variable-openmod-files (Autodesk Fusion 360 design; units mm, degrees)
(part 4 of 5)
sketch "50mm PM Label" plane through (0, 0, 0) normal (0, 0, -1) x axis (1, 0, 0)
  line L1 (1, -18.9737) -> (1, -23.9792)
  line L2 (14.6475, -19.0119) -> (11.43, -15.1775)
  line L3 (9.9868, 4.6112) -> (6.5, 2.5981)
  line L4 (1, -6.9282) -> (1, -10.9545)
  line L5 (1, 16.9706) -> (1, 12.9615)
  line L6 (10.725, 7.3468) -> (14.1969, 9.3513)
  line L7 (-8.9868, 6.3433) -> (-5.5, 4.3301)
  line L8 (5.5, 4.3301) -> (8.9868, 6.3433)
  line L9 (-1, -16.9706) -> (-1, -12.9615)
  line L10 (-10.725, -7.3468) -> (-14.1969, -9.3513)
  line L11 (-11.725, 5.6147) -> (-15.1969, 7.6193)
  line L12 (-15.1969, -7.6193) -> (-11.725, -5.6147)
  line L13 (11.725, -5.6147) -> (15.1969, -7.6193)
  line L14 (15.1969, 7.6193) -> (11.725, 5.6147)
  line L15 (1, -12.9615) -> (1, -16.9706)
  line L16 (14.1969, -9.3513) -> (10.725, -7.3468)
  line L17 (-1, 12.9615) -> (-1, 16.9706)
  line L18 (-14.1969, 9.3513) -> (-10.725, 7.3468)
  line L19 (-1, -10.9545) -> (-1, -6.9282)
  line L20 (-6.5, 2.5981) -> (-9.9868, 4.6112)
  line L21 (-11.43, -15.1775) -> (-14.6475, -19.0119)
  line L22 (-1, -23.9792) -> (-1, -18.9737)
  line L23 (-18.5118, -4.2796) -> (-23.4412, -5.1487)
  line L24 (-16.1795, -17.7263) -> (-12.9621, -13.8919)
  line L25 (-16.9317, 8.6208) -> (-21.2666, 11.1236)
  line L26 (-23.7885, -3.1791) -> (-18.8591, -2.3099)
  line L27 (-7.4291, 17.4874) -> (-9.141, 22.191)
  line L28 (-20.2666, 12.8556) -> (-15.9317, 10.3529)
  line L29 (5.5497, 18.1714) -> (7.2617, 22.8751)
  line L30 (-7.2617, 22.8751) -> (-5.5497, 18.1714)
  line L31 (15.9317, 10.3529) -> (20.2666, 12.8556)
  line L32 (9.141, 22.191) -> (7.4291, 17.4874)
  line L33 (18.8591, -2.3099) -> (23.7885, -3.1791)
  line L34 (21.2666, 11.1236) -> (16.9317, 8.6208)
  line L35 (12.9621, -13.8919) -> (16.1795, -17.7263)
  line L36 (23.4412, -5.1487) -> (18.5118, -4.2796)
  line L37 (27.3973, 19.1838) -> (24.0432, 16.8352)
  line L38 (24.0432, -16.8352) -> (27.3973, -19.1838)
  line L39 (-17.7523, 28.4096) -> (-15.6326, 25.0174)
  line L40 (15.6326, 25.0174) -> (17.7523, 28.4096)
  line L41 (-27.3973, -19.1838) -> (-24.0432, -16.8352)
  line L42 (-24.0432, 16.8352) -> (-27.3973, 19.1838)
  line L43 (17.7523, -28.4096) -> (15.6326, -25.0174)
  line L44 (-15.6326, -25.0174) -> (-17.7523, -28.4096)
  curve K1 (0, 52) -> (0, 52)
  curve K2
  curve K3
  curve K4
  curve K5
  arc A1 centre (0, 0) radius 19 clockwise from (11.43, -15.1775) to (1, -18.9737)
  arc A2 centre (0, 0) radius 24 clockwise from (14.6475, -19.0119) to (1, -23.9792)
  arc A3 centre (0, 0) radius 11 clockwise from (9.9868, 4.6112) to (1, -10.9545)
  arc A4 centre (0, 0) radius 7 clockwise from (6.5, 2.5981) to (1, -6.9282)
  arc A5 centre (0, 0) radius 17 clockwise from (1, 16.9706) to (14.1969, 9.3513)
  arc A6 centre (0, 0) radius 13 clockwise from (1, 12.9615) to (10.725, 7.3468)
  circle C1 centre (0, 0) radius 5
  arc A7 centre (0, 0) radius 11 clockwise from (-8.9868, 6.3433) to (8.9868, 6.3433)
  arc A8 centre (0, 0) radius 7 clockwise from (-5.5, 4.3301) to (5.5, 4.3301)
  arc A9 centre (0, 0) radius 17 clockwise from (-1, -16.9706) to (-14.1969, -9.3513)
  arc A10 centre (0, 0) radius 13 clockwise from (-1, -12.9615) to (-10.725, -7.3468)
  arc A11 centre (0, 0) radius 17 clockwise from (-15.1969, -7.6193) to (-15.1969, 7.6193)
  arc A12 centre (0, 0) radius 13 clockwise from (-11.725, -5.6147) to (-11.725, 5.6147)
  arc A13 centre (0, 0) radius 17 clockwise from (15.1969, 7.6193) to (15.1969, -7.6193)
  arc A14 centre (0, 0) radius 13 clockwise from (11.725, 5.6147) to (11.725, -5.6147)
  arc A15 centre (0, 0) radius 17 clockwise from (14.1969, -9.3513) to (1, -16.9706)
  arc A16 centre (0, 0) radius 13 clockwise from (10.725, -7.3468) to (1, -12.9615)
  arc A17 centre (0, 0) radius 17 clockwise from (-14.1969, 9.3513) to (-1, 16.9706)
  arc A18 centre (0, 0) radius 13 clockwise from (-10.725, 7.3468) to (-1, 12.9615)
  arc A19 centre (0, 0) radius 11 clockwise from (-1, -10.9545) to (-9.9868, 4.6112)
  arc A20 centre (0, 0) radius 7 clockwise from (-1, -6.9282) to (-6.5, 2.5981)
  arc A21 centre (0, 0) radius 19 clockwise from (-1, -18.9737) to (-11.43, -15.1775)
  arc A22 centre (0, 0) radius 24 clockwise from (-1, -23.9792) to (-14.6475, -19.0119)
  arc A23 centre (0, 0) radius 19 clockwise from (-12.9621, -13.8919) to (-18.5118, -4.2796)
  arc A24 centre (0, 0) radius 24 clockwise from (-16.1795, -17.7263) to (-23.4412, -5.1487)
  arc A25 centre (0, 0) radius 19 clockwise from (-18.8591, -2.3099) to (-16.9317, 8.6208)
  arc A26 centre (0, 0) radius 24 clockwise from (-23.7885, -3.1791) to (-21.2666, 11.1236)
  arc A27 centre (0, 0) radius 19 clockwise from (-15.9317, 10.3529) to (-7.4291, 17.4874)
  arc A28 centre (0, 0) radius 24 clockwise from (-20.2666, 12.8556) to (-9.141, 22.191)
  arc A29 centre (0, 0) radius 19 clockwise from (-5.5497, 18.1714) to (5.5497, 18.1714)
  arc A30 centre (0, 0) radius 24 clockwise from (-7.2617, 22.8751) to (7.2617, 22.8751)
  arc A31 centre (0, 0) radius 19 clockwise from (7.4291, 17.4874) to (15.9317, 10.3529)
  arc A32 centre (0, 0) radius 24 clockwise from (9.141, 22.191) to (20.2666, 12.8556)
  arc A33 centre (0, 0) radius 19 clockwise from (16.9317, 8.6208) to (18.8591, -2.3099)
  arc A34 centre (0, 0) radius 24 clockwise from (21.2666, 11.1236) to (23.7885, -3.1791)
  arc A35 centre (0, 0) radius 24 clockwise from (23.4412, -5.1487) to (16.1795, -17.7263)
  arc A36 centre (0, 0) radius 19 clockwise from (18.5118, -4.2796) to (12.9621, -13.8919)
  closed curve K6 centre (0, 0)
  closed curve K7 centre (0, 0)
  arc A37 centre (0, 0) radius 33.5 clockwise from (-17.7523, 28.4096) to (17.7523, 28.4096)
  arc A38 centre (0, 0) radius 29.5 clockwise from (-15.6326, 25.0174) to (15.6326, 25.0174)
  closed curve K8 centre (0, 0)
  closed curve K9 centre (0, 0)
  arc A39 centre (0, 0) radius 33.5 clockwise from (17.7523, -28.4096) to (-17.7523, -28.4096)
  arc A40 centre (0, 0) radius 29.5 clockwise from (15.6326, -25.0174) to (-15.6326, -25.0174)
  circle C2 centre (-22.8469, 24.5003) radius 4
  circle C3 centre (22.8469, 24.5003) radius 4
  circle C4 centre (-22.8469, -24.5003) radius 4
  circle C5 centre (22.8469, -24.5003) radius 4
  coincident K1
  dimension "d517" Text1-Height = 10
extrude "Extrude28" cut sketch "50mm PM Label" against normal blind 0.5
sketch "50mm DC Label" plane through (0, 0, 20) normal (0, 0, -1) x axis (1, 0, 0)
  line L1 (8, 23.8964) -> (8, 32.5308)
  line L2 (-8, 32.5308) -> (-8, 23.8964)
  line L3 (27.3973, 19.1838) -> (24.0432, 16.8352)
  line L4 (24.0432, -16.8352) -> (27.3973, -19.1838)
  line L5 (17.7523, -28.4096) -> (15.6326, -25.0174)
  line L6 (-15.6326, -25.0174) -> (-17.7523, -28.4096)
  line L7 (-27.3973, -19.1838) -> (-24.0432, -16.8352)
  line L8 (-24.0432, 16.8352) -> (-27.3973, 19.1838)
  line L9 (6, 55.0308) -> (8, 54.1239)
  line L10 (-6, 55.0308) -> (6, 55.0308)
  line L11 (-8, 54.1239) -> (-6, 55.0308)
  curve K1
  curve K2
  curve K3
  curve K4
  line L12 (45, -1.2179) -> (45, -5.5)
  line L13 (48, -1.2179) -> (45, -1.2179)
  line L14 (48, 3.5) -> (48, -1.2179)
  line L15 (45, 3.5) -> (48, 3.5)
  line L16 (45, 5.5) -> (45, 3.5)
  line L17 (44.7744, 5.5) -> (45, 5.5)
  line L18 (-45, 5.5) -> (-44.7744, 5.5)
  line L19 (-45, 3.5) -> (-45, 5.5)
  line L20 (-48, 3.5) -> (-45, 3.5)
  line L21 (-48, -1.2179) -> (-48, 3.5)
  line L22 (-45, -1.2179) -> (-48, -1.2179)
  line L23 (-45, -5.5) -> (-45, -1.2179)
  line L24 (-44.7744, -5.5) -> (-45, -5.5)
  line L25 (45, -5.5) -> (44.7744, -5.5)
  arc A1 centre (0, 0) radius 25.2 clockwise from (8, 23.8964) to (-8, 23.8964)
  arc A2 centre (0, 0) radius 33.5 clockwise from (-8, 32.5308) to (8, 32.5308)
  closed curve K5 centre (0, 0)
  closed curve K6 centre (0, 0)
  arc A3 centre (0, 0) radius 27.5 clockwise from (26.4189, 7.6348) to (26.4189, -7.6348)
  closed curve K7 centre (0, 0)
  circle C1 centre (22.8469, -24.5003) radius 2.2
  circle C2 centre (22.8469, 24.5003) radius 2.2
  circle C3 centre (-22.8469, -24.5003) radius 2.2
  circle C4 centre (-22.8469, 24.5003) radius 2.2
  arc A4 centre (0, 0) radius 33.5 clockwise from (17.7523, -28.4096) to (-17.7523, -28.4096)
  arc A5 centre (0, 0) radius 29.5 clockwise from (15.6326, -25.0174) to (-15.6326, -25.0174)
  closed curve K8 centre (0, 0)
  closed curve K9 centre (0, 0)
  closed curve K10 centre (0, 0)
  closed curve K11 centre (0, 0)
  arc A6 centre (0, 0) radius 27.5 clockwise from (-26.4189, -7.6348) to (-26.4189, 7.6348)
  closed curve K12 centre (0, 0)
  closed curve K13 centre (0, 0)
  dimension "d520" Text1-Height = 10
extrude "Extrude29" cut sketch "50mm DC Label" against normal blind 0.5
sketch "52mm PM Label" plane through (0, 0, 0) normal (0, 0, -1) x axis (1, 0, 0)
  line L1 (101, -19.975) -> (101, -24.98)
  line L2 (115.2908, -19.7786) -> (112.0736, -15.9445)
  line L3 (109.9868, 4.6112) -> (106.5, 2.5981)
  line L4 (101, -6.9282) -> (101, -10.9545)
  line L5 (101, 17.9722) -> (101, 12.9615)
  line L6 (110.725, 7.3468) -> (115.0644, 9.8521)
  line L7 (91.0132, 6.3433) -> (94.5, 4.3301)
  line L8 (105.5, 4.3301) -> (108.9868, 6.3433)
  line L9 (99, -17.9722) -> (99, -12.9615)
  line L10 (89.275, -7.3468) -> (84.9356, -9.8521)
  line L11 (88.275, 5.6147) -> (83.9356, 8.1201)
  line L12 (83.9356, -8.1201) -> (88.275, -5.6147)
  line L13 (111.725, -5.6147) -> (116.0644, -8.1201)
  line L14 (116.0644, 8.1201) -> (111.725, 5.6147)
  line L15 (101, -12.9615) -> (101, -17.9722)
  line L16 (115.0644, -9.8521) -> (110.725, -7.3468)
  line L17 (99, 12.9615) -> (99, 17.9722)
  line L18 (84.9356, 9.8521) -> (89.275, 7.3468)
  line L19 (99, -10.9545) -> (99, -6.9282)
  line L20 (93.5, 2.5981) -> (90.0132, 4.6112)
  line L21 (87.9264, -15.9445) -> (84.7092, -19.7786)
  line L22 (99, -24.98) -> (99, -19.975)
  line L23 (80.5021, -4.4534) -> (75.5732, -5.3225)
  line L24 (83.1771, -18.493) -> (86.3943, -14.6589)
  line L25 (82.2012, 9.1215) -> (77.8667, 11.624)
  line L26 (75.2259, -3.3529) -> (80.1548, -2.4838)
  line L27 (92.2285, 18.4283) -> (90.5166, 23.1315)
  line L28 (78.8667, 13.356) -> (83.2012, 10.8535)
  line L29 (105.8922, 19.1124) -> (107.604, 23.8155)
  line L30 (92.396, 23.8155) -> (94.1078, 19.1124)
  line L31 (116.7988, 10.8535) -> (121.1333, 13.356)
  line L32 (109.4834, 23.1315) -> (107.7715, 18.4283)
  line L33 (119.8452, -2.4838) -> (124.7741, -3.3529)
  line L34 (122.1333, 11.624) -> (117.7988, 9.1215)
  line L35 (113.6057, -14.6589) -> (116.8229, -18.493)
  line L36 (124.4268, -5.3225) -> (119.4979, -4.4534)
  line L37 (127.3973, 19.1838) -> (124.8888, 17.4274)
  line L38 (124.8888, -17.4274) -> (127.3973, -19.1838)
  curve K1 (124.8888, -17.4274) -> (124.8888, 17.4274)
  line L39 (82.2477, 28.4096) -> (84.3674, 25.0174)
  line L40 (115.6326, 25.0174) -> (117.7523, 28.4096)
  line L41 (72.6027, -19.1838) -> (75.1112, -17.4274)
  line L42 (75.1112, 17.4274) -> (72.6027, 19.1838)
  curve K2 (75.1112, 17.4274) -> (75.1112, -17.4274)
  line L43 (117.7523, -28.4096) -> (115.6326, -25.0174)
  line L44 (84.3674, -25.0174) -> (82.2477, -28.4096)
  curve K3 (100, 52) -> (100, 52)
  curve K4
  curve K5
  curve K6
  curve K7
  arc A1 centre (100, 0) radius 20 clockwise from (112.0736, -15.9445) to (101, -19.975)
  arc A2 centre (100, 0) radius 25 clockwise from (115.2908, -19.7786) to (101, -24.98)
  arc A3 centre (100, 0) radius 11 clockwise from (109.9868, 4.6112) to (101, -10.9545)
  arc A4 centre (100, 0) radius 7 clockwise from (106.5, 2.5981) to (101, -6.9282)
  arc A5 centre (100, 0) radius 18 clockwise from (101, 17.9722) to (115.0644, 9.8521)
  arc A6 centre (100, 0) radius 13 clockwise from (101, 12.9615) to (110.725, 7.3468)
  circle C1 centre (100, 0) radius 5
  arc A7 centre (100, 0) radius 11 clockwise from (91.0132, 6.3433) to (108.9868, 6.3433)
  arc A8 centre (100, 0) radius 7 clockwise from (94.5, 4.3301) to (105.5, 4.3301)
  arc A9 centre (100, 0) radius 18 clockwise from (99, -17.9722) to (84.9356, -9.8521)
  arc A10 centre (100, 0) radius 13 clockwise from (99, -12.9615) to (89.275, -7.3468)
  arc A11 centre (100, 0) radius 18 clockwise from (83.9356, -8.1201) to (83.9356, 8.1201)
  arc A12 centre (100, 0) radius 13 clockwise from (88.275, -5.6147) to (88.275, 5.6147)
  arc A13 centre (100, 0) radius 18 clockwise from (116.0644, 8.1201) to (116.0644, -8.1201)
  arc A14 centre (100, 0) radius 13 clockwise from (111.725, 5.6147) to (111.725, -5.6147)
  arc A15 centre (100, 0) radius 18 clockwise from (115.0644, -9.8521) to (101, -17.9722)
  arc A16 centre (100, 0) radius 13 clockwise from (110.725, -7.3468) to (101, -12.9615)
  arc A17 centre (100, 0) radius 18 clockwise from (84.9356, 9.8521) to (99, 17.9722)
  arc A18 centre (100, 0) radius 13 clockwise from (89.275, 7.3468) to (99, 12.9615)
  arc A19 centre (100, 0) radius 11 clockwise from (99, -10.9545) to (90.0132, 4.6112)
  arc A20 centre (100, 0) radius 7 clockwise from (99, -6.9282) to (93.5, 2.5981)
  arc A21 centre (100, 0) radius 20 clockwise from (99, -19.975) to (87.9264, -15.9445)
  arc A22 centre (100, 0) radius 25 clockwise from (99, -24.98) to (84.7092, -19.7786)
  arc A23 centre (100, 0) radius 20 clockwise from (86.3943, -14.6589) to (80.5021, -4.4534)
  arc A24 centre (100, 0) radius 25 clockwise from (83.1771, -18.493) to (75.5732, -5.3225)
  arc A25 centre (100, 0) radius 20 clockwise from (80.1548, -2.4838) to (82.2012, 9.1215)
  arc A26 centre (100, 0) radius 25 clockwise from (75.2259, -3.3529) to (77.8667, 11.624)
  arc A27 centre (100, 0) radius 20 clockwise from (83.2012, 10.8535) to (92.2285, 18.4283)
  arc A28 centre (100, 0) radius 25 clockwise from (78.8667, 13.356) to (90.5166, 23.1315)
  arc A29 centre (100, 0) radius 20 clockwise from (94.1078, 19.1124) to (105.8922, 19.1124)
  arc A30 centre (100, 0) radius 25 clockwise from (92.396, 23.8155) to (107.604, 23.8155)
  arc A31 centre (100, 0) radius 20 clockwise from (107.7715, 18.4283) to (116.7988, 10.8535)
  arc A32 centre (100, 0) radius 25 clockwise from (109.4834, 23.1315) to (121.1333, 13.356)
  arc A33 centre (100, 0) radius 20 clockwise from (117.7988, 9.1215) to (119.8452, -2.4838)
  arc A34 centre (100, 0) radius 25 clockwise from (122.1333, 11.624) to (124.7741, -3.3529)
  arc A35 centre (100, 0) radius 25 clockwise from (124.4268, -5.3225) to (116.8229, -18.493)
  arc A36 centre (100, 0) radius 20 clockwise from (119.4979, -4.4534) to (113.6057, -14.6589)
  closed curve K8 centre (100, 0)
  arc A37 centre (100, 0) radius 33.5 clockwise from (82.2477, 28.4096) to (117.7523, 28.4096)
  arc A38 centre (100, 0) radius 29.5 clockwise from (84.3674, 25.0174) to (115.6326, 25.0174)
  closed curve K9 centre (100, 0)
  arc A39 centre (100, 0) radius 33.5 clockwise from (117.7523, -28.4096) to (82.2477, -28.4096)
  arc A40 centre (100, 0) radius 29.5 clockwise from (115.6326, -25.0174) to (84.3674, -25.0174)
  circle C2 centre (77.1531, 24.5003) radius 4
  circle C3 centre (122.8469, 24.5003) radius 4
  circle C4 centre (77.1531, -24.5003) radius 4
  circle C5 centre (122.8469, -24.5003) radius 4
  dimension "d523" Text1-Height = 10
sketch "52mm DC Label" plane through (0, 0, 20) normal (0, 0, -1) x axis (1, 0, 0)
  line L1 (117.7523, -28.4096) -> (115.6326, -25.0174)
  line L2 (84.3674, -25.0174) -> (82.2477, -28.4096)
  curve K1 (124.8888, 17.4274) -> (127.1497, 9.3052)
  line L3 (127.3973, 19.1838) -> (124.8888, 17.4274)
  line L4 (124.8888, -17.4274) -> (127.3973, -19.1838)
  curve K2 (127.1497, -9.3052) -> (124.8888, -17.4274)
  line L5 (108, 24.9487) -> (108, 32.5308)
  line L6 (92, 32.5308) -> (92, 24.9487)
  curve K3 (75.1112, -17.4274) -> (72.8503, -9.3052)
  line L7 (72.6027, -19.1838) -> (75.1112, -17.4274)
  line L8 (75.1112, 17.4274) -> (72.6027, 19.1838)
  curve K4 (72.8503, 9.3052) -> (75.1112, 17.4274)
  line L9 (106, 55.0308) -> (108, 54.1239)
  line L10 (94, 55.0308) -> (106, 55.0308)
  line L11 (92, 54.1239) -> (94, 55.0308)
  curve K5
  curve K6
  curve K7
  curve K8
  line L12 (145, -1.2179) -> (145, -5.5)
  line L13 (148, -1.2179) -> (145, -1.2179)
  line L14 (148, 3.5) -> (148, -1.2179)
  line L15 (145, 3.5) -> (148, 3.5)
  line L16 (145, 5.5) -> (145, 3.5)
  line L17 (144.7744, 5.5) -> (145, 5.5)
  line L18 (55, 5.5) -> (55.2256, 5.5)
  line L19 (55, 3.5) -> (55, 5.5)
  line L20 (52, 3.5) -> (55, 3.5)
  line L21 (52, -1.2179) -> (52, 3.5)
  line L22 (55, -1.2179) -> (52, -1.2179)
  line L23 (55, -5.5) -> (55, -1.2179)
  line L24 (55.2256, -5.5) -> (55, -5.5)
  line L25 (145, -5.5) -> (144.7744, -5.5)
  arc A1 centre (100, 0) radius 33.5 clockwise from (117.7523, -28.4096) to (82.2477, -28.4096)
  arc A2 centre (100, 0) radius 29.5 clockwise from (115.6326, -25.0174) to (84.3674, -25.0174)
  closed curve K9 centre (100, 0)
  arc A3 centre (100, 0) radius 28.7 clockwise from (127.1497, 9.3052) to (127.1497, -9.3052)
  arc A4 centre (100, 0) radius 26.2 clockwise from (108, 24.9487) to (92, 24.9487)
  arc A5 centre (100, 0) radius 33.5 clockwise from (92, 32.5308) to (108, 32.5308)
  closed curve K10 centre (100, 0)
  arc A6 centre (100, 0) radius 28.7 clockwise from (72.8503, -9.3052) to (72.8503, 9.3052)
  circle C1 centre (122.8469, -24.5003) radius 2.2
  circle C2 centre (122.8469, 24.5003) radius 2.2
  circle C3 centre (77.1531, -24.5003) radius 2.2
  circle C4 centre (77.1531, 24.5003) radius 2.2
  closed curve K11 centre (100, 0)
  closed curve K12 centre (100, 0)
  closed curve K13 centre (100, 0)
  dimension "d524" Text1-Height = 10
extrude "Extrude14" cut sketch "52mm PM Label" against normal blind 0.5
extrude "Extrude15" cut sketch "52mm DC Label" against normal blind 0.5
sketch "40mm PM Label" plane through (0, 0, 0) normal (0, 0, -1) x axis (1, 0, 0)
  line L1 (-1, -130.9545) -> (-1, -126.9282)
  line L2 (-6.5, -117.4019) -> (-9.9868, -115.3888)
  line L3 (-1, -107.0385) -> (-1, -103.0294)
  line L4 (-14.1969, -110.6487) -> (-10.725, -112.6532)
  line L5 (1, -132.9615) -> (1, -136.9706)
  line L6 (14.1969, -129.3513) -> (10.725, -127.3468)
  line L7 (11.725, -125.6147) -> (15.1969, -127.6193)
  line L8 (15.1969, -112.3807) -> (11.725, -114.3853)
  line L9 (-11.725, -114.3853) -> (-15.1969, -112.3807)
  line L10 (-15.1969, -127.6193) -> (-11.725, -125.6147)
  line L11 (-1, -136.9706) -> (-1, -132.9615)
  line L12 (-10.725, -127.3468) -> (-14.1969, -129.3513)
  line L13 (-8.9868, -113.6567) -> (-5.5, -115.6699)
  line L14 (5.5, -115.6699) -> (8.9868, -113.6567)
  line L15 (1, -103.0294) -> (1, -107.0385)
  line L16 (10.725, -112.6532) -> (14.1969, -110.6487)
  line L17 (9.9868, -115.3888) -> (6.5, -117.4019)
  line L18 (1, -126.9282) -> (1, -130.9545)
  line L19 (27.3973, -100.8162) -> (24.0432, -103.1648)
  line L20 (24.0432, -136.8352) -> (27.3973, -139.1838)
  line L21 (-17.7523, -91.5904) -> (-15.6326, -94.9826)
  line L22 (15.6326, -94.9826) -> (17.7523, -91.5904)
  line L23 (-27.3973, -139.1838) -> (-24.0432, -136.8352)
  line L24 (-24.0432, -103.1648) -> (-27.3973, -100.8162)
  line L25 (17.7523, -148.4096) -> (15.6326, -145.0174)
  line L26 (-15.6326, -145.0174) -> (-17.7523, -148.4096)
  curve K1 (0, -68) -> (0, -68)
  curve K2
  curve K3
  curve K4
  curve K5
  arc A1 centre (0, -120) radius 11 clockwise from (-1, -130.9545) to (-9.9868, -115.3888)
  arc A2 centre (0, -120) radius 7 clockwise from (-1, -126.9282) to (-6.5, -117.4019)
  arc A3 centre (0, -120) radius 17 clockwise from (-14.1969, -110.6487) to (-1, -103.0294)
  arc A4 centre (0, -120) radius 13 clockwise from (-10.725, -112.6532) to (-1, -107.0385)
  arc A5 centre (0, -120) radius 17 clockwise from (14.1969, -129.3513) to (1, -136.9706)
  arc A6 centre (0, -120) radius 13 clockwise from (10.725, -127.3468) to (1, -132.9615)
  arc A7 centre (0, -120) radius 17 clockwise from (15.1969, -112.3807) to (15.1969, -127.6193)
  arc A8 centre (0, -120) radius 13 clockwise from (11.725, -114.3853) to (11.725, -125.6147)
  arc A9 centre (0, -120) radius 17 clockwise from (-15.1969, -127.6193) to (-15.1969, -112.3807)
  arc A10 centre (0, -120) radius 13 clockwise from (-11.725, -125.6147) to (-11.725, -114.3853)
  arc A11 centre (0, -120) radius 17 clockwise from (-1, -136.9706) to (-14.1969, -129.3513)
  arc A12 centre (0, -120) radius 13 clockwise from (-1, -132.9615) to (-10.725, -127.3468)
  arc A13 centre (0, -120) radius 11 clockwise from (-8.9868, -113.6567) to (8.9868, -113.6567)
  arc A14 centre (0, -120) radius 7 clockwise from (-5.5, -115.6699) to (5.5, -115.6699)
  circle C1 centre (0, -120) radius 5
  arc A15 centre (0, -120) radius 17 clockwise from (1, -103.0294) to (14.1969, -110.6487)
  arc A16 centre (0, -120) radius 13 clockwise from (1, -107.0385) to (10.725, -112.6532)
  arc A17 centre (0, -120) radius 11 clockwise from (9.9868, -115.3888) to (1, -130.9545)
  arc A18 centre (0, -120) radius 7 clockwise from (6.5, -117.4019) to (1, -126.9282)
  closed curve K6 centre (0, -120)
  closed curve K7 centre (0, -120)
  arc A19 centre (0, -120) radius 33.5 clockwise from (-17.7523, -91.5904) to (17.7523, -91.5904)
  arc A20 centre (0, -120) radius 29.5 clockwise from (-15.6326, -94.9826) to (15.6326, -94.9826)
  closed curve K8 centre (0, -120)
  closed curve K9 centre (0, -120)
  arc A21 centre (0, -120) radius 33.5 clockwise from (17.7523, -148.4096) to (-17.7523, -148.4096)
  arc A22 centre (0, -120) radius 29.5 clockwise from (15.6326, -145.0174) to (-15.6326, -145.0174)
  circle C2 centre (-22.8469, -95.4997) radius 4
  circle C3 centre (22.8469, -95.4997) radius 4
  circle C4 centre (-22.8469, -144.5003) radius 4
  circle C5 centre (22.8469, -144.5003) radius 4
  dimension "d529" Text1-Height = 10
sketch "40mm DC Label" plane through (0, 0, 20) normal (0, 0, -1) x axis (1, 0, 0)
  line L1 (8, -101.1254) -> (8, -92.6458)
  line L2 (-8, -92.6458) -> (-8, -101.1254)
  line L3 (27.3973, -100.8162) -> (24.0432, -103.1648)
  line L4 (24.0432, -136.8352) -> (27.3973, -139.1838)
  line L5 (17.7523, -148.4096) -> (15.6326, -145.0174)
  line L6 (-15.6326, -145.0174) -> (-17.7523, -148.4096)
  line L7 (-27.3973, -139.1838) -> (-24.0432, -136.8352)
  line L8 (-24.0432, -103.1648) -> (-27.3973, -100.8162)
  line L9 (6, -64.9692) -> (8, -65.8761)
  line L10 (-6, -64.9692) -> (6, -64.9692)
  line L11 (-8, -65.8761) -> (-6, -64.9692)
  curve K1
  curve K2
  curve K3
  curve K4
  line L12 (45, -121.2179) -> (45, -125.5)
  line L13 (48, -121.2179) -> (45, -121.2179)
  line L14 (48, -116.5) -> (48, -121.2179)
  line L15 (45, -116.5) -> (48, -116.5)
  line L16 (45, -114.5) -> (45, -116.5)
  line L17 (44.7744, -114.5) -> (45, -114.5)
  line L18 (-45, -114.5) -> (-44.7744, -114.5)
  line L19 (-45, -116.5) -> (-45, -114.5)
  line L20 (-48, -116.5) -> (-45, -116.5)
  line L21 (-48, -121.2179) -> (-48, -116.5)
  line L22 (-45, -121.2179) -> (-48, -121.2179)
  line L23 (-45, -125.5) -> (-45, -121.2179)
  line L24 (-44.7744, -125.5) -> (-45, -125.5)
  line L25 (45, -125.5) -> (44.7744, -125.5)
  arc A1 centre (0, -120) radius 20.5 clockwise from (8, -101.1254) to (-8, -101.1254)
  arc A2 centre (0, -120) radius 28.5 clockwise from (-8, -92.6458) to (8, -92.6458)
  closed curve K5 centre (0, -120)
  closed curve K6 centre (0, -120)
  arc A3 centre (0, -120) radius 27.5 clockwise from (26.4189, -112.3652) to (26.4189, -127.6348)
  closed curve K7 centre (0, -120)
  circle C1 centre (22.8469, -144.5003) radius 2.2
  circle C2 centre (22.8469, -95.4997) radius 2.2
  circle C3 centre (-22.8469, -144.5003) radius 2.2
  circle C4 centre (-22.8469, -95.4997) radius 2.2
  arc A4 centre (0, -120) radius 33.5 clockwise from (17.7523, -148.4096) to (-17.7523, -148.4096)
  arc A5 centre (0, -120) radius 29.5 clockwise from (15.6326, -145.0174) to (-15.6326, -145.0174)
  closed curve K8 centre (0, -120)
  arc A6 centre (0, -120) radius 27.5 clockwise from (-26.4189, -127.6348) to (-26.4189, -112.3652)
  closed curve K9 centre (0, -120)
  closed curve K10 centre (0, -120)
  closed curve K11 centre (0, -120)
  closed curve K12 centre (0, -120)
  closed curve K13 centre (0, -120)
  dimension "d530" Text1-Height = 10
extrude "Extrude16" cut sketch "40mm DC Label" against normal blind 0.5
extrude "Extrude17" cut sketch "40mm PM Label" against normal blind 0.5
sketch "44mm PM Label" plane through (0, 0, 0) normal (0, 0, -1) x axis (1, 0, 0)
  line L1 (101, -138.9737) -> (101, -140.9762)
  line L2 (112.7172, -136.7115) -> (111.43, -135.1775)
  line L3 (109.9868, -115.3888) -> (106.5, -117.4019)
  line L4 (101, -126.9282) -> (101, -130.9545)
  line L5 (101, -103.0294) -> (101, -107.0385)
  line L6 (110.725, -112.6532) -> (114.1969, -110.6487)
  line L7 (91.0132, -113.6567) -> (94.5, -115.6699)
  line L8 (105.5, -115.6699) -> (108.9868, -113.6567)
  line L9 (99, -136.9706) -> (99, -132.9615)
  line L10 (89.275, -127.3468) -> (85.8031, -129.3513)
  line L11 (88.275, -114.3853) -> (84.8031, -112.3807)
  line L12 (84.8031, -127.6193) -> (88.275, -125.6147)
  line L13 (111.725, -125.6147) -> (115.1969, -127.6193)
  line L14 (115.1969, -112.3807) -> (111.725, -114.3853)
  line L15 (101, -132.9615) -> (101, -136.9706)
  line L16 (114.1969, -129.3513) -> (110.725, -127.3468)
  line L17 (99, -107.0385) -> (99, -103.0294)
  line L18 (85.8031, -110.6487) -> (89.275, -112.6532)
  line L19 (99, -130.9545) -> (99, -126.9282)
  line L20 (93.5, -117.4019) -> (90.0132, -115.3888)
  line L21 (88.57, -135.1775) -> (87.2828, -136.7115)
  line L22 (99, -140.9762) -> (99, -138.9737)
  line L23 (81.4882, -124.2796) -> (79.5161, -124.6273)
  line L24 (85.7507, -135.4259) -> (87.0379, -133.8919)
  line L25 (83.0683, -111.3792) -> (81.3341, -110.3779)
  line L26 (79.1689, -122.6577) -> (81.1409, -122.3099)
  line L27 (92.5709, -102.5126) -> (91.886, -100.6309)
  line L28 (82.3341, -108.6459) -> (84.0683, -109.6471)
  line L29 (105.5497, -101.8286) -> (106.2346, -99.9468)
  line L30 (93.7654, -99.9468) -> (94.4503, -101.8286)
  line L31 (115.9317, -109.6471) -> (117.6659, -108.6459)
  line L32 (108.114, -100.6309) -> (107.4291, -102.5126)
  line L33 (118.8591, -122.3099) -> (120.8311, -122.6577)
  line L34 (118.6659, -110.3779) -> (116.9317, -111.3792)
  line L35 (112.9621, -133.8919) -> (114.2493, -135.4259)
  line L36 (120.4839, -124.6273) -> (118.5118, -124.2796)
  line L37 (127.3973, -100.8162) -> (124.0432, -103.1648)
  line L38 (124.0432, -136.8352) -> (127.3973, -139.1838)
  line L39 (82.2477, -91.5904) -> (84.3674, -94.9826)
  line L40 (115.6326, -94.9826) -> (117.7523, -91.5904)
  line L41 (72.6027, -139.1838) -> (75.9568, -136.8352)
  line L42 (75.9568, -103.1648) -> (72.6027, -100.8162)
  line L43 (117.7523, -148.4096) -> (115.6326, -145.0174)
  line L44 (84.3674, -145.0174) -> (82.2477, -148.4096)
  curve K1 (100, -68) -> (100, -68)
  curve K2
  curve K3
  curve K4
  curve K5
  arc A1 centre (100, -120) radius 19 clockwise from (111.43, -135.1775) to (101, -138.9737)
  arc A2 centre (100, -120) radius 21 clockwise from (112.7172, -136.7115) to (101, -140.9762)
  arc A3 centre (100, -120) radius 11 clockwise from (109.9868, -115.3888) to (101, -130.9545)
  arc A4 centre (100, -120) radius 7 clockwise from (106.5, -117.4019) to (101, -126.9282)
  arc A5 centre (100, -120) radius 17 clockwise from (101, -103.0294) to (114.1969, -110.6487)
  arc A6 centre (100, -120) radius 13 clockwise from (101, -107.0385) to (110.725, -112.6532)
  circle C1 centre (100, -120) radius 5
  arc A7 centre (100, -120) radius 11 clockwise from (91.0132, -113.6567) to (108.9868, -113.6567)
  arc A8 centre (100, -120) radius 7 clockwise from (94.5, -115.6699) to (105.5, -115.6699)
  arc A9 centre (100, -120) radius 17 clockwise from (99, -136.9706) to (85.8031, -129.3513)
  arc A10 centre (100, -120) radius 13 clockwise from (99, -132.9615) to (89.275, -127.3468)
  arc A11 centre (100, -120) radius 17 clockwise from (84.8031, -127.6193) to (84.8031, -112.3807)
  arc A12 centre (100, -120) radius 13 clockwise from (88.275, -125.6147) to (88.275, -114.3853)
  arc A13 centre (100, -120) radius 17 clockwise from (115.1969, -112.3807) to (115.1969, -127.6193)
  arc A14 centre (100, -120) radius 13 clockwise from (111.725, -114.3853) to (111.725, -125.6147)
  arc A15 centre (100, -120) radius 17 clockwise from (114.1969, -129.3513) to (101, -136.9706)
  arc A16 centre (100, -120) radius 13 clockwise from (110.725, -127.3468) to (101, -132.9615)
  arc A17 centre (100, -120) radius 17 clockwise from (85.8031, -110.6487) to (99, -103.0294)
  arc A18 centre (100, -120) radius 13 clockwise from (89.275, -112.6532) to (99, -107.0385)
  arc A19 centre (100, -120) radius 11 clockwise from (99, -130.9545) to (90.0132, -115.3888)
  arc A20 centre (100, -120) radius 7 clockwise from (99, -126.9282) to (93.5, -117.4019)
  arc A21 centre (100, -120) radius 19 clockwise from (99, -138.9737) to (88.57, -135.1775)
  arc A22 centre (100, -120) radius 21 clockwise from (99, -140.9762) to (87.2828, -136.7115)
  arc A23 centre (100, -120) radius 19 clockwise from (87.0379, -133.8919) to (81.4882, -124.2796)
  arc A24 centre (100, -120) radius 21 clockwise from (85.7507, -135.4259) to (79.5161, -124.6273)
  arc A25 centre (100, -120) radius 19 clockwise from (81.1409, -122.3099) to (83.0683, -111.3792)
  arc A26 centre (100, -120) radius 21 clockwise from (79.1689, -122.6577) to (81.3341, -110.3779)
  arc A27 centre (100, -120) radius 19 clockwise from (84.0683, -109.6471) to (92.5709, -102.5126)
  arc A28 centre (100, -120) radius 21 clockwise from (82.3341, -108.6459) to (91.886, -100.6309)
  arc A29 centre (100, -120) radius 19 clockwise from (94.4503, -101.8286) to (105.5497, -101.8286)
  arc A30 centre (100, -120) radius 21 clockwise from (93.7654, -99.9468) to (106.2346, -99.9468)
  arc A31 centre (100, -120) radius 19 clockwise from (107.4291, -102.5126) to (115.9317, -109.6471)
  arc A32 centre (100, -120) radius 21 clockwise from (108.114, -100.6309) to (117.6659, -108.6459)
  arc A33 centre (100, -120) radius 19 clockwise from (116.9317, -111.3792) to (118.8591, -122.3099)
  arc A34 centre (100, -120) radius 21 clockwise from (118.6659, -110.3779) to (120.8311, -122.6577)
  arc A35 centre (100, -120) radius 21 clockwise from (120.4839, -124.6273) to (114.2493, -135.4259)
  arc A36 centre (100, -120) radius 19 clockwise from (118.5118, -124.2796) to (112.9621, -133.8919)
  closed curve K6 centre (100, -120)
  closed curve K7 centre (100, -120)
  arc A37 centre (100, -120) radius 33.5 clockwise from (82.2477, -91.5904) to (117.7523, -91.5904)
  arc A38 centre (100, -120) radius 29.5 clockwise from (84.3674, -94.9826) to (115.6326, -94.9826)
  closed curve K8 centre (100, -120)
  closed curve K9 centre (100, -120)
  arc A39 centre (100, -120) radius 33.5 clockwise from (117.7523, -148.4096) to (82.2477, -148.4096)
  arc A40 centre (100, -120) radius 29.5 clockwise from (115.6326, -145.0174) to (84.3674, -145.0174)
  circle C2 centre (77.1531, -95.4997) radius 4
  circle C3 centre (122.8469, -95.4997) radius 4
  circle C4 centre (77.1531, -144.5003) radius 4
  circle C5 centre (122.8469, -144.5003) radius 4
  dimension "d535" Text1-Height = 10
sketch "44mm DC Label" plane through (0, 0, 20) normal (0, 0, -1) x axis (1, 0, 0)
  line L1 (108, -99.2915) -> (108, -87.4692)
  line L2 (92, -87.4692) -> (92, -99.2915)
  line L3 (127.3973, -100.8162) -> (124.0432, -103.1648)
  line L4 (124.0432, -136.8352) -> (127.3973, -139.1838)
  line L5 (117.7523, -148.4096) -> (115.6326, -145.0174)
  line L6 (84.3674, -145.0174) -> (82.2477, -148.4096)
  line L7 (72.6027, -139.1838) -> (75.9568, -136.8352)
  line L8 (75.9568, -103.1648) -> (72.6027, -100.8162)
  line L9 (106, -64.9692) -> (108, -65.8761)
  line L10 (94, -64.9692) -> (106, -64.9692)
  line L11 (92, -65.8761) -> (94, -64.9692)
  curve K1
  curve K2
  curve K3
  curve K4
  line L12 (145, -121.2179) -> (145, -125.5)
  line L13 (148, -121.2179) -> (145, -121.2179)
  line L14 (148, -116.5) -> (148, -121.2179)
  line L15 (145, -116.5) -> (148, -116.5)
  line L16 (145, -114.5) -> (145, -116.5)
  line L17 (144.7744, -114.5) -> (145, -114.5)
  line L18 (55, -114.5) -> (55.2256, -114.5)
  line L19 (55, -116.5) -> (55, -114.5)
  line L20 (52, -116.5) -> (55, -116.5)
  line L21 (52, -121.2179) -> (52, -116.5)
  line L22 (55, -121.2179) -> (52, -121.2179)
  line L23 (55, -125.5) -> (55, -121.2179)
  line L24 (55.2256, -125.5) -> (55, -125.5)
  line L25 (145, -125.5) -> (144.7744, -125.5)
  arc A1 centre (100, -120) radius 22.2 clockwise from (108, -99.2915) to (92, -99.2915)
  arc A2 centre (100, -120) radius 33.5 clockwise from (92, -87.4692) to (108, -87.4692)
  closed curve K5 centre (100, -120)
  closed curve K6 centre (100, -120)
  arc A3 centre (100, -120) radius 27.5 clockwise from (126.4189, -112.3652) to (126.4189, -127.6348)
  closed curve K7 centre (100, -120)
  circle C1 centre (122.8469, -144.5003) radius 2.2
  circle C2 centre (122.8469, -95.4997) radius 2.2
  circle C3 centre (77.1531, -144.5003) radius 2.2
  circle C4 centre (77.1531, -95.4997) radius 2.2
  arc A4 centre (100, -120) radius 33.5 clockwise from (117.7523, -148.4096) to (82.2477, -148.4096)
  arc A5 centre (100, -120) radius 29.5 clockwise from (115.6326, -145.0174) to (84.3674, -145.0174)
  closed curve K8 centre (100, -120)
  closed curve K9 centre (100, -120)
  closed curve K10 centre (100, -120)
  closed curve K11 centre (100, -120)
  arc A6 centre (100, -120) radius 27.5 clockwise from (73.5811, -127.6348) to (73.5811, -112.3652)
  closed curve K12 centre (100, -120)
  closed curve K13 centre (100, -120)
  dimension "d536" Text1-Height = 10
extrude "Extrude18" cut sketch "44mm PM Label" against normal blind 0.5
extrude "Extrude19" cut sketch "44mm DC Label" against normal blind 0.5
sketch "45mm PM Label" plane through (0, 0, 0) normal (0, 0, -1) x axis (1, 0, 0)
  line L1 (201, -138.9737) -> (201, -141.4767)
  line L2 (213.0389, -137.0949) -> (211.43, -135.1775)
  line L3 (209.9868, -115.3888) -> (206.5, -117.4019)
  line L4 (201, -126.9282) -> (201, -130.9545)
  line L5 (201, -103.0294) -> (201, -107.0385)
  line L6 (210.725, -112.6532) -> (214.1969, -110.6487)
  line L7 (191.0132, -113.6567) -> (194.5, -115.6699)
  line L8 (205.5, -115.6699) -> (208.9868, -113.6567)
  line L9 (199, -136.9706) -> (199, -132.9615)
  line L10 (189.275, -127.3468) -> (185.8031, -129.3513)
  line L11 (188.275, -114.3853) -> (184.8031, -112.3807)
  line L12 (184.8031, -127.6193) -> (188.275, -125.6147)
  line L13 (211.725, -125.6147) -> (215.1969, -127.6193)
  line L14 (215.1969, -112.3807) -> (211.725, -114.3853)
  line L15 (201, -132.9615) -> (201, -136.9706)
  line L16 (214.1969, -129.3513) -> (210.725, -127.3468)
  line L17 (199, -107.0385) -> (199, -103.0294)
  line L18 (185.8031, -110.6487) -> (189.275, -112.6532)
  line L19 (199, -130.9545) -> (199, -126.9282)
  line L20 (193.5, -117.4019) -> (190.0132, -115.3888)
  line L21 (188.57, -135.1775) -> (186.9611, -137.0949)
  line L22 (199, -141.4767) -> (199, -138.9737)
  line L23 (181.4882, -124.2796) -> (179.0232, -124.7142)
  line L24 (185.429, -135.8093) -> (187.0379, -133.8919)
  line L25 (183.0683, -111.3792) -> (180.9006, -110.1277)
  line L26 (178.6759, -122.7446) -> (181.1409, -122.3099)
  line L27 (192.5709, -102.5126) -> (191.7148, -100.1605)
  line L28 (181.9006, -108.3956) -> (184.0683, -109.6471)
  line L29 (205.5497, -101.8286) -> (206.4058, -99.4765)
  line L30 (193.5942, -99.4765) -> (194.4503, -101.8286)
  line L31 (215.9317, -109.6471) -> (218.0994, -108.3956)
  line L32 (208.2852, -100.1605) -> (207.4291, -102.5126)
  line L33 (218.8591, -122.3099) -> (221.3241, -122.7446)
  line L34 (219.0994, -110.1277) -> (216.9317, -111.3792)
  line L35 (212.9621, -133.8919) -> (214.571, -135.8093)
  line L36 (220.9768, -124.7142) -> (218.5118, -124.2796)
  line L37 (227.3973, -100.8162) -> (224.0432, -103.1648)
  line L38 (224.0432, -136.8352) -> (227.3973, -139.1838)
  line L39 (182.2477, -91.5904) -> (184.3674, -94.9826)
  line L40 (215.6326, -94.9826) -> (217.7523, -91.5904)
  line L41 (172.6027, -139.1838) -> (175.9568, -136.8352)
  line L42 (175.9568, -103.1648) -> (172.6027, -100.8162)
  line L43 (217.7523, -148.4096) -> (215.6326, -145.0174)
  line L44 (184.3674, -145.0174) -> (182.2477, -148.4096)
  curve K1 (200, -68) -> (200, -68)
  curve K2
  curve K3
  curve K4
  curve K5
  arc A1 centre (200, -120) radius 19 clockwise from (211.43, -135.1775) to (201, -138.9737)
  arc A2 centre (200, -120) radius 21.5 clockwise from (213.0389, -137.0949) to (201, -141.4767)
  arc A3 centre (200, -120) radius 11 clockwise from (209.9868, -115.3888) to (201, -130.9545)
  arc A4 centre (200, -120) radius 7 clockwise from (206.5, -117.4019) to (201, -126.9282)
  arc A5 centre (200, -120) radius 17 clockwise from (201, -103.0294) to (214.1969, -110.6487)
  arc A6 centre (200, -120) radius 13 clockwise from (201, -107.0385) to (210.725, -112.6532)
  circle C1 centre (200, -120) radius 5
  arc A7 centre (200, -120) radius 11 clockwise from (191.0132, -113.6567) to (208.9868, -113.6567)
  arc A8 centre (200, -120) radius 7 clockwise from (194.5, -115.6699) to (205.5, -115.6699)
  arc A9 centre (200, -120) radius 17 clockwise from (199, -136.9706) to (185.8031, -129.3513)
  arc A10 centre (200, -120) radius 13 clockwise from (199, -132.9615) to (189.275, -127.3468)
  arc A11 centre (200, -120) radius 17 clockwise from (184.8031, -127.6193) to (184.8031, -112.3807)
  arc A12 centre (200, -120) radius 13 clockwise from (188.275, -125.6147) to (188.275, -114.3853)
  arc A13 centre (200, -120) radius 17 clockwise from (215.1969, -112.3807) to (215.1969, -127.6193)
  arc A14 centre (200, -120) radius 13 clockwise from (211.725, -114.3853) to (211.725, -125.6147)
  arc A15 centre (200, -120) radius 17 clockwise from (214.1969, -129.3513) to (201, -136.9706)
  arc A16 centre (200, -120) radius 13 clockwise from (210.725, -127.3468) to (201, -132.9615)
  arc A17 centre (200, -120) radius 17 clockwise from (185.8031, -110.6487) to (199, -103.0294)
  arc A18 centre (200, -120) radius 13 clockwise from (189.275, -112.6532) to (199, -107.0385)
  arc A19 centre (200, -120) radius 11 clockwise from (199, -130.9545) to (190.0132, -115.3888)
  arc A20 centre (200, -120) radius 7 clockwise from (199, -126.9282) to (193.5, -117.4019)
  arc A21 centre (200, -120) radius 19 clockwise from (199, -138.9737) to (188.57, -135.1775)
  arc A22 centre (200, -120) radius 21.5 clockwise from (199, -141.4767) to (186.9611, -137.0949)
  arc A23 centre (200, -120) radius 19 clockwise from (187.0379, -133.8919) to (181.4882, -124.2796)
  arc A24 centre (200, -120) radius 21.5 clockwise from (185.429, -135.8093) to (179.0232, -124.7142)
  arc A25 centre (200, -120) radius 19 clockwise from (181.1409, -122.3099) to (183.0683, -111.3792)
  arc A26 centre (200, -120) radius 21.5 clockwise from (178.6759, -122.7446) to (180.9006, -110.1277)
  arc A27 centre (200, -120) radius 19 clockwise from (184.0683, -109.6471) to (192.5709, -102.5126)
  arc A28 centre (200, -120) radius 21.5 clockwise from (181.9006, -108.3956) to (191.7148, -100.1605)
  arc A29 centre (200, -120) radius 19 clockwise from (194.4503, -101.8286) to (205.5497, -101.8286)
  arc A30 centre (200, -120) radius 21.5 clockwise from (193.5942, -99.4765) to (206.4058, -99.4765)
  arc A31 centre (200, -120) radius 19 clockwise from (207.4291, -102.5126) to (215.9317, -109.6471)
  arc A32 centre (200, -120) radius 21.5 clockwise from (208.2852, -100.1605) to (218.0994, -108.3956)
  arc A33 centre (200, -120) radius 19 clockwise from (216.9317, -111.3792) to (218.8591, -122.3099)
  arc A34 centre (200, -120) radius 21.5 clockwise from (219.0994, -110.1277) to (221.3241, -122.7446)
  arc A35 centre (200, -120) radius 21.5 clockwise from (220.9768, -124.7142) to (214.571, -135.8093)
  arc A36 centre (200, -120) radius 19 clockwise from (218.5118, -124.2796) to (212.9621, -133.8919)
  closed curve K6 centre (200, -120)
  closed curve K7 centre (200, -120)
  arc A37 centre (200, -120) radius 33.5 clockwise from (182.2477, -91.5904) to (217.7523, -91.5904)
  arc A38 centre (200, -120) radius 29.5 clockwise from (184.3674, -94.9826) to (215.6326, -94.9826)
  closed curve K8 centre (200, -120)
  closed curve K9 centre (200, -120)
  arc A39 centre (200, -120) radius 33.5 clockwise from (217.7523, -148.4096) to (182.2477, -148.4096)
  arc A40 centre (200, -120) radius 29.5 clockwise from (215.6326, -145.0174) to (184.3674, -145.0174)
  circle C2 centre (177.1531, -95.4997) radius 4
  circle C3 centre (222.8469, -95.4997) radius 4
  circle C4 centre (177.1531, -144.5003) radius 4
  circle C5 centre (222.8469, -144.5003) radius 4
  dimension "d541" Text1-Height = 10
extrude "Extrude20" cut sketch "45mm PM Label" against normal blind 0.5
sketch "45mm DC Label" plane through (0, 0, 20) normal (0, 0, -1) x axis (1, 0, 0)
  line L1 (208, -98.7564) -> (208, -87.4692)
  line L2 (192, -87.4692) -> (192, -98.7564)
  line L3 (227.3973, -100.8162) -> (224.0432, -103.1648)
  line L4 (224.0432, -136.8352) -> (227.3973, -139.1838)
  line L5 (217.7523, -148.4096) -> (215.6326, -145.0174)
  line L6 (184.3674, -145.0174) -> (182.2477, -148.4096)
  line L7 (172.6027, -139.1838) -> (175.9568, -136.8352)
  line L8 (175.9568, -103.1648) -> (172.6027, -100.8162)
  line L9 (206, -64.9692) -> (208, -65.8761)
  line L10 (194, -64.9692) -> (206, -64.9692)
  line L11 (192, -65.8761) -> (194, -64.9692)
  curve K1
  curve K2
  curve K3
  curve K4
  line L12 (245, -121.2179) -> (245, -125.5)
  line L13 (248, -121.2179) -> (245, -121.2179)
  line L14 (248, -116.5) -> (248, -121.2179)
  line L15 (245, -116.5) -> (248, -116.5)
  line L16 (245, -114.5) -> (245, -116.5)
  line L17 (244.7744, -114.5) -> (245, -114.5)
  line L18 (155, -114.5) -> (155.2256, -114.5)
  line L19 (155, -116.5) -> (155, -114.5)
  line L20 (152, -116.5) -> (155, -116.5)
  line L21 (152, -121.2179) -> (152, -116.5)
  line L22 (155, -121.2179) -> (152, -121.2179)
  line L23 (155, -125.5) -> (155, -121.2179)
  line L24 (155.2256, -125.5) -> (155, -125.5)
  line L25 (245, -125.5) -> (244.7744, -125.5)
  arc A1 centre (200, -120) radius 22.7 clockwise from (208, -98.7564) to (192, -98.7564)
  arc A2 centre (200, -120) radius 33.5 clockwise from (192, -87.4692) to (208, -87.4692)
  closed curve K5 centre (200, -120)
  closed curve K6 centre (200, -120)
  arc A3 centre (200, -120) radius 27.5 clockwise from (226.4189, -112.3652) to (226.4189, -127.6348)
  closed curve K7 centre (200, -120)
  circle C1 centre (222.8469, -144.5003) radius 2.2
  circle C2 centre (222.8469, -95.4997) radius 2.2
  circle C3 centre (177.1531, -144.5003) radius 2.2
  circle C4 centre (177.1531, -95.4997) radius 2.2
  arc A4 centre (200, -120) radius 33.5 clockwise from (217.7523, -148.4096) to (182.2477, -148.4096)
  arc A5 centre (200, -120) radius 29.5 clockwise from (215.6326, -145.0174) to (184.3674, -145.0174)
  closed curve K8 centre (200, -120)
  closed curve K9 centre (200, -120)
  closed curve K10 centre (200, -120)
  closed curve K11 centre (200, -120)
  arc A6 centre (200, -120) radius 27.5 clockwise from (173.5811, -127.6348) to (173.5811, -112.3652)
  closed curve K12 centre (200, -120)
  closed curve K13 centre (200, -120)
  dimension "d544" Text1-Height = 10
extrude "Extrude21" cut sketch "45mm DC Label" against normal blind 0.5
sketch "Sketch18" plane through (0, -134.6, 0) normal (0, -1, 0) x axis (1, 0, 0)
  line L1 (-1.5, 9.5) -> (-1.5, 7)
  line L2 (1.5, 9.5) -> (-1.5, 9.5)
  line L3 (1.5, 7) -> (1.5, 9.5)
  line L4 (-1.5, 7) -> (1.5, 7)
  line L5 (-3.6, 6) -> (-3.6, 2)
  line L6 (3.6, 6) -> (-3.6, 6)
  line L7 (3.6, 2) -> (3.6, 6)
  line L8 (-3.6, 2) -> (3.6, 2)
  line L9 (18, 0) -> (-18, 0)
  line L10 (18, 10) -> (18, 0)
  line L11 (4, 10) -> (18, 10)
  line L12 (2, 12) -> (4, 10)
  line L13 (-2, 12) -> (2, 12)
  line L14 (-4, 10) -> (-2, 12)
  line L15 (-18, 10) -> (-4, 10)
  line L16 (-18, 0) -> (-18, 10)
  line L17 (5.8, 0) -> (18, 0)
  line L18 (5.8, 4) -> (5.8, 0)
  line L19 (18, 4) -> (5.8, 4)
  line L20 (18, 0) -> (18, 4)
  line L21 (9.8, 4) -> (5.8, 0)
  line L22 (11.4569, 0) -> (5.8, 0)
  line L23 (18, 2) -> (5.8, 2)
  line L24 (3.6, 2) -> (5.8, 2)
  line L25 (3.6, 4) -> (3.6, 2)
  line L26 (5.8, 4) -> (3.6, 4)
  line L27 (5.8, 2) -> (5.8, 4)
  point P11 (18, 0)
  point P18 (18, 0)
  point P22 (9.8, 4)
  point P24 (5.8, 2)
  point P25 (18, 2)
  point P27 (3.6, 4)
  point P19 (5.8, 0)
  point P21 (18, 4)
  horizontal L17
  vertical L18
  horizontal L19
  vertical L20
  coincident P11 P18
  horizontal L22
  coincident L19 P22
  midpoint L18 P24
  midpoint L20 P25
  horizontal L24
  vertical L25
  horizontal L26
  vertical L27
  midpoint L7 P27
  dimension "d634" distance P18 P19 = 12.2
  dimension "d635" distance P18 P21 = 4
  dimension "d636" angle L21 L22 = 45
extrude "Extrude34" cut sketch "Sketch18" profile of L9 L10 L17 L19 L20 L21 L23 against normal blind 9.2
extrude "Extrude35" cut sketch "Sketch18" profile of L7 L18 L19 L21 L23 L24 L25 L26 L27 against normal blind 4
sketch "Sketch19" plane through (-3.6, 0, 0) normal (1, 0, 0) x axis (0, 1, 0)
  line L1 (-126.9215, 2) -> (-134.6, 2)
  line L2 (-126.9215, 6) -> (-126.9215, 2)
  line L3 (-134.6, 6) -> (-126.9215, 6)
  line L4 (-134.6, 2) -> (-134.6, 6)
  line L5 (-130.6, 2) -> (-134.6, 2)
  line L6 (-130.6, 4) -> (-130.6, 2)
  line L7 (-134.6, 4) -> (-130.6, 4)
  line L8 (-134.6, 2) -> (-134.6, 4)
  line L9 (-133.1, 2) -> (-133.1, 4)
  line L10 (-132.1, 2) -> (-132.1, 4)
  line L11 (-132.1, 4) -> (-133.1, 3)
  line L12 (-132.1, 2) -> (-133.1, 3)
  point P2 (-134.6, 2)
  point P6 (-134.6, 2)
  point P14 (-133.1, 3)
  point P7 (-130.6, 2)
  point P9 (-134.6, 4)
  horizontal L5
  vertical L6
  horizontal L7
  parallel L6 L8
  coincident P2 P6
  midpoint L9 P14
  perpendicular L11 L12
  dimension "d641" distance P6 P7 = 4
  dimension "d642" distance P6 P9 = 2
  dimension "d643" = -1.5
  dimension "d644" = -2.5
extrude "Extrude36" cut sketch "Sketch19" profile of L1 L5 L6 L7 L11 L12 against normal blind 14.4
chamfer "Chamfer10" distance 1
sketch "Sketch20" plane through (130.0009, -75.0561, 0) normal (-0.866, 0.5, 0) x axis (-0.5, -0.866, 0)
  line L1 (120.3942, 1) -> (113.3942, 1)
  line L2 (120.3942, 35) -> (120.3942, 1)
  line L3 (113.3942, 35) -> (120.3942, 35)
  line L4 (113.3942, 1) -> (113.3942, 35)
  line L5 (109.3942, 35) -> (120.3942, 35)
  line L6 (109.3942, 27.6) -> (109.3942, 35)
  line L7 (120.3942, 27.6) -> (109.3942, 27.6)
  line L8 (120.3942, 35) -> (120.3942, 27.6)
  line L9 (113.3942, 23.6) -> (109.3942, 27.6)
  line L10 (115.051, 27.6) -> (109.3942, 27.6)
  line L11 (120.3942, 35) -> (109.3942, 35)
  line L12 (120.3942, 36) -> (120.3942, 35)
  line L13 (109.3942, 36) -> (120.3942, 36)
  line L14 (109.3942, 35) -> (109.3942, 36)
  line L15 (113.3942, 36) -> (113.3942, 35)
  point P4 (120.3942, 35)
  point P6 (120.3942, 35)
  point P10 (113.3942, 23.6)
  point P5 (113.3942, 35)
  point P15 (113.3942, 35)
  point P16 (113.3942, 36)
  point P7 (109.3942, 35)
  point P9 (120.3942, 27.6)
  point P12 (120.3942, 35)
  point P14 (109.3942, 36)
  horizontal L5
  vertical L6
  horizontal L7
  vertical L8
  coincident P4 P6
  horizontal L10
  coincident L4 P10
  horizontal L11
  vertical L12
  horizontal L13
  vertical L14
  coincident P5 P15
  coincident L13 P16
  perpendicular L13 L15
  dimension "d648" distance P6 P7 = 11
  dimension "d649" distance P6 P9 = 7.4
  dimension "d650" angle L9 L10 = 45
  dimension "d651" distance P7 P12 = 11
  dimension "d652" distance P7 P14 = 1
extrude "Extrude37" add sketch "Sketch20" profile of L4 L5 L6 L7 L9 L11 L13 L14 L15 against normal blind 9.2
extrude "Extrude38" cut of existing geometry blind -4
